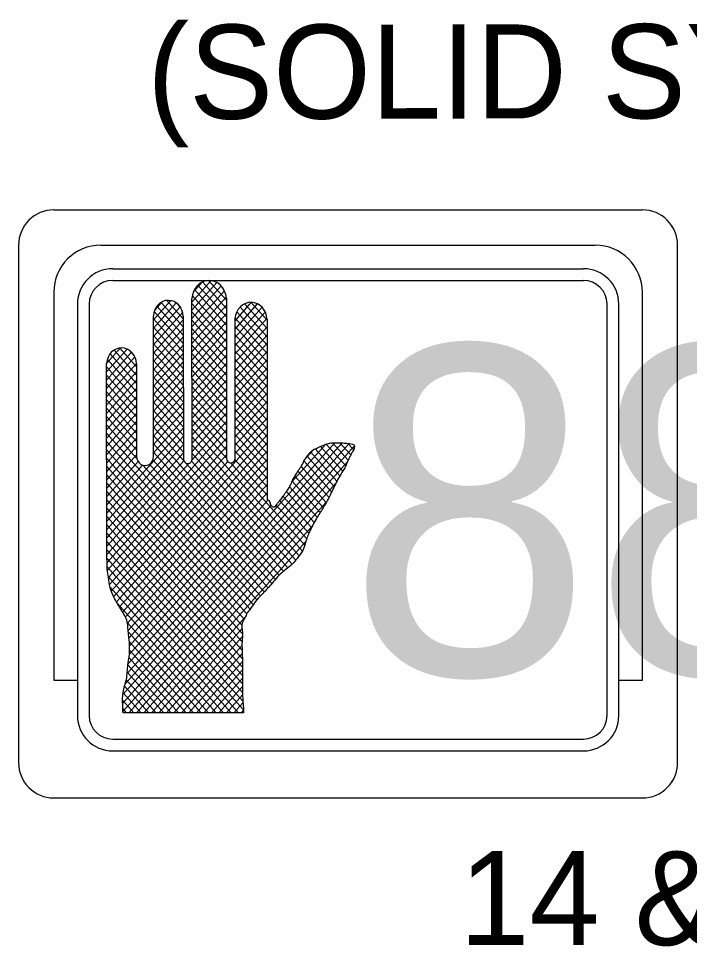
# Model space of a CAD drawing. Extents: x 660636 to 661659, y 641779 to 643841.
# Drawn here: x 660982.79 to 661011.29, y 642847.57 to 642887.02 of the extents above; entities that cross this region are included whole.
import ezdxf

# ---------------------------------------------------------------- set-up
doc = ezdxf.new("R2010")
doc.units = 0
doc.layers.add('Default', color=7, linetype='Continuous')
doc.layers.add('T_Drafting', color=7, linetype='Continuous')

msp = doc.modelspace()

# ---------------------------------------------------------------- linework, layer by layer
at = {"layer": 'T_Drafting'}
for p, q in [((660984.288, 642878.883), (661009.288, 642878.883)), ((660982.788, 642877.383), (660982.788, 642855.383)), ((660986.288, 642877.383), (661007.288, 642877.383)), ((661010.788, 642855.383), (661010.788, 642877.383)), ((660986.788, 642876.383), (661006.788, 642876.383)), ((660986.788, 642875.883), (661006.788, 642875.883)), ((660990.152, 642874.967), (660990.974, 642875.88)), ((660990.153, 642874.614), (660991.218, 642875.797)), ((660990.153, 642874.261), (660991.402, 642875.649)), ((660990.206, 642875.38), (660990.607, 642875.826)), ((660990.403, 642875.687), (660991.616, 642874.339)), ((660990.599, 642875.823), (660991.616, 642874.693)), ((660990.86, 642875.886), (660991.616, 642875.047)), ((660991.327, 642875.721), (660991.469, 642875.564)), ((660984.288, 642875.383), (660984.288, 642858.883)), ((660990.154, 642873.908), (660991.536, 642875.444)), ((660990.167, 642875.242), (660991.617, 642873.631)), ((660990.258, 642875.495), (660991.617, 642873.985)), ((661009.288, 642858.883), (661009.288, 642875.383)), ((660985.288, 642874.883), (660985.288, 642857.383)), ((660985.788, 642874.883), (660985.788, 642857.383)), ((660988.514, 642874.208), (660989.251, 642875.027)), ((660988.515, 642873.855), (660989.484, 642874.931)), ((660988.571, 642874.625), (660988.882, 642874.97)), ((660988.842, 642874.947), (660989.788, 642873.896)), ((660989.084, 642875.032), (660989.787, 642874.25)), ((660989.509, 642874.913), (660989.678, 642874.725)), ((660990.16, 642868.283), (660990.152, 642875.11)), ((660990.152, 642874.905), (660991.618, 642873.277)), ((660990.154, 642873.555), (660991.612, 642875.174)), ((660991.615, 642875.129), (660991.623, 642868.351)), ((660991.983, 642874.172), (660992.688, 642874.956)), ((660991.983, 642873.819), (660992.945, 642874.888)), ((660992.39, 642874.894), (660993.344, 642873.834)), ((660992.651, 642874.957), (660993.344, 642874.188)), ((661007.788, 642857.383), (661007.788, 642874.883)), ((661008.288, 642857.383), (661008.288, 642874.883)), ((660988.515, 642873.501), (660989.652, 642874.765)), ((660988.515, 642873.148), (660989.761, 642874.532)), ((660988.549, 642874.565), (660989.788, 642873.188)), ((660988.666, 642874.789), (660989.788, 642873.542)), ((660990.153, 642874.551), (660991.618, 642872.923)), ((660990.154, 642873.202), (660991.616, 642874.826)), ((660990.155, 642872.849), (660991.616, 642874.473)), ((660991.983, 642873.466), (660993.135, 642874.745)), ((660991.984, 642873.113), (660993.27, 642874.542)), ((660992.059, 642874.554), (660993.345, 642873.126)), ((660992.197, 642874.754), (660993.344, 642873.48)), ((660988.521, 642868.41), (660988.514, 642874.375)), ((660988.514, 642874.251), (660989.789, 642872.834)), ((660988.516, 642872.795), (660989.787, 642874.208)), ((660989.787, 642874.361), (660989.793, 642868.315)), ((660990.153, 642874.197), (660991.618, 642872.569)), ((660990.155, 642872.495), (660991.617, 642874.119)), ((660991.989, 642868.318), (660991.983, 642874.266)), ((660991.984, 642874.284), (660993.345, 642872.772)), ((660991.984, 642872.76), (660993.341, 642874.268)), ((660993.344, 642874.219), (660993.352, 642866.562)), ((660988.514, 642873.897), (660989.789, 642872.48)), ((660988.516, 642872.442), (660989.788, 642873.855)), ((660990.154, 642873.843), (660991.619, 642872.215)), ((660990.156, 642872.142), (660991.617, 642873.766)), ((660991.983, 642873.932), (660993.345, 642872.418)), ((660991.985, 642872.407), (660993.344, 642873.917)), ((660988.515, 642873.543), (660989.79, 642872.126)), ((660988.517, 642872.089), (660989.788, 642873.502)), ((660990.154, 642873.489), (660991.619, 642871.861)), ((660990.156, 642871.789), (660991.618, 642873.413)), ((660991.983, 642873.578), (660993.346, 642872.064)), ((660991.985, 642872.054), (660993.344, 642873.564)), ((660986.526, 642872.352), (660987.121, 642873.014)), ((660986.526, 642871.999), (660987.396, 642872.966)), ((660986.846, 642872.922), (660987.8, 642871.862)), ((660987.085, 642873.01), (660987.799, 642872.216)), ((660987.488, 642872.916), (660987.71, 642872.669)), ((660988.515, 642873.189), (660989.79, 642871.772)), ((660988.517, 642871.736), (660989.789, 642873.149)), ((660990.154, 642873.135), (660991.62, 642871.507)), ((660990.156, 642871.436), (660991.618, 642873.06)), ((660991.984, 642873.224), (660993.346, 642871.71)), ((660991.984, 642872.87), (660993.346, 642871.356)), ((660991.985, 642871.701), (660993.345, 642873.211)), ((660986.527, 642871.646), (660987.592, 642872.83)), ((660986.527, 642871.293), (660987.73, 642872.629)), ((660986.558, 642872.535), (660987.8, 642871.154)), ((660986.673, 642872.761), (660987.8, 642871.508)), ((660988.516, 642872.835), (660989.79, 642871.418)), ((660988.516, 642872.481), (660989.791, 642871.064)), ((660988.517, 642871.383), (660989.789, 642872.796)), ((660990.155, 642872.781), (660991.62, 642871.153)), ((660990.157, 642871.083), (660991.618, 642872.707)), ((660991.984, 642872.516), (660993.347, 642871.002)), ((660991.986, 642871.347), (660993.345, 642872.858)), ((660991.986, 642870.994), (660993.345, 642872.505)), ((660986.535, 642864.112), (660986.526, 642872.355)), ((660986.526, 642872.217), (660987.801, 642870.8)), ((660986.527, 642870.94), (660987.799, 642872.352)), ((660987.799, 642872.34), (660987.803, 642868.409)), ((660988.516, 642872.127), (660989.791, 642870.71)), ((660988.518, 642871.03), (660989.789, 642872.443)), ((660988.518, 642870.677), (660989.79, 642872.089)), ((660990.155, 642872.427), (660991.62, 642870.799)), ((660990.156, 642872.073), (660991.621, 642870.445)), ((660990.157, 642870.73), (660991.619, 642872.354)), ((660991.985, 642872.162), (660993.347, 642870.648)), ((660991.987, 642870.641), (660993.346, 642872.151)), ((660986.526, 642871.863), (660987.801, 642870.446)), ((660986.528, 642870.586), (660987.8, 642871.999)), ((660988.517, 642871.773), (660989.792, 642870.356)), ((660988.519, 642870.323), (660989.79, 642871.736)), ((660990.156, 642871.719), (660991.621, 642870.091)), ((660990.158, 642870.377), (660991.619, 642872.001)), ((660991.985, 642871.808), (660993.348, 642870.294)), ((660991.987, 642870.288), (660993.346, 642871.798)), ((660986.527, 642871.509), (660987.802, 642870.092)), ((660986.528, 642870.233), (660987.8, 642871.646)), ((660986.529, 642869.88), (660987.8, 642871.293)), ((660988.517, 642871.419), (660989.792, 642870.002)), ((660988.519, 642869.97), (660989.791, 642871.383)), ((660990.156, 642871.365), (660991.622, 642869.737)), ((660990.158, 642870.024), (660991.619, 642871.648)), ((660990.158, 642869.671), (660991.62, 642871.295)), ((660991.986, 642871.454), (660993.348, 642869.94)), ((660991.987, 642869.935), (660993.346, 642871.445)), ((660986.527, 642871.155), (660987.802, 642869.738)), ((660986.529, 642869.527), (660987.801, 642870.94)), ((660988.518, 642871.065), (660989.792, 642869.648)), ((660988.519, 642869.617), (660989.791, 642871.03)), ((660990.157, 642871.011), (660991.622, 642869.383)), ((660990.159, 642869.317), (660991.62, 642870.941)), ((660991.986, 642871.1), (660993.348, 642869.586)), ((660991.988, 642869.582), (660993.347, 642871.092)), ((660986.528, 642870.801), (660987.802, 642869.384)), ((660986.529, 642869.174), (660987.801, 642870.587)), ((660988.518, 642870.711), (660989.793, 642869.294)), ((660988.52, 642869.264), (660989.791, 642870.677)), ((660990.157, 642870.657), (660991.622, 642869.029)), ((660990.159, 642868.964), (660991.621, 642870.588)), ((660991.986, 642870.746), (660993.349, 642869.232)), ((660991.988, 642869.229), (660993.347, 642870.739)), ((660986.528, 642870.447), (660987.803, 642869.03)), ((660986.53, 642868.821), (660987.802, 642870.234)), ((660988.518, 642870.357), (660989.793, 642868.94)), ((660988.52, 642868.911), (660989.792, 642870.324)), ((660990.158, 642870.303), (660991.623, 642868.675)), ((660990.16, 642868.611), (660991.621, 642870.235)), ((660991.987, 642870.392), (660993.349, 642868.878)), ((660991.989, 642868.876), (660993.347, 642870.386)), ((660986.528, 642870.093), (660987.803, 642868.676)), ((660986.529, 642869.739), (660987.815, 642868.31)), ((660986.53, 642868.468), (660987.802, 642869.881)), ((660988.519, 642870.003), (660989.794, 642868.586)), ((660988.521, 642868.558), (660989.792, 642869.971)), ((660990.156, 642868.254), (660991.621, 642869.882)), ((660990.158, 642869.949), (660991.618, 642868.327)), ((660991.987, 642870.038), (660993.349, 642868.524)), ((660991.989, 642868.523), (660993.348, 642870.032)), ((660986.529, 642869.385), (660992.907, 642862.299)), ((660986.53, 642868.115), (660987.802, 642869.528)), ((660986.533, 642865.996), (660989.793, 642869.618)), ((660986.547, 642863.89), (660991.622, 642869.529)), ((660986.828, 642862.434), (660993.348, 642869.679)), ((660986.951, 642862.218), (660993.349, 642869.326)), ((660988.519, 642869.649), (660989.81, 642868.215)), ((660990.158, 642869.595), (660994.852, 642864.38)), ((660991.988, 642869.684), (660993.35, 642868.171)), ((660991.988, 642869.33), (660993.35, 642867.817)), ((660986.53, 642869.031), (660992.759, 642862.109)), ((660986.531, 642867.761), (660987.803, 642869.175)), ((660986.533, 642865.643), (660989.793, 642869.265)), ((660986.558, 642863.549), (660991.622, 642869.176)), ((660987.076, 642862.003), (660993.349, 642868.973)), ((660987.221, 642858.275), (660996.826, 642868.948)), ((660987.326, 642858.745), (660996.537, 642868.98)), ((660987.396, 642859.177), (660996.219, 642868.98)), ((660988.52, 642869.295), (660993.866, 642863.354)), ((660988.52, 642868.941), (660993.709, 642863.175)), ((660990.159, 642869.241), (660994.713, 642864.181)), ((660991.988, 642868.976), (660993.35, 642867.463)), ((660994.39, 642867.302), (660995.846, 642868.919)), ((660995.855, 642868.923), (660996.686, 642867.999)), ((660996.121, 642868.98), (660996.788, 642868.24)), ((660996.439, 642868.98), (660996.901, 642868.468)), ((660996.781, 642868.954), (660997.012, 642868.698)), ((660986.53, 642868.677), (660992.625, 642861.905)), ((660986.531, 642867.408), (660987.803, 642868.821)), ((660986.534, 642865.289), (660989.793, 642868.911)), ((660986.534, 642864.936), (660989.794, 642868.558)), ((660986.607, 642863.25), (660991.623, 642868.823)), ((660987.2, 642861.787), (660993.349, 642868.62)), ((660987.211, 642857.91), (660997.057, 642868.85)), ((660988.52, 642868.587), (660993.553, 642862.995)), ((660990.159, 642868.887), (660994.563, 642863.994)), ((660990.16, 642868.533), (660994.406, 642863.815)), ((660991.989, 642868.622), (660993.351, 642867.109)), ((660994.992, 642868.323), (660995.334, 642868.703)), ((660995.197, 642868.592), (660996.314, 642867.352)), ((660995.395, 642868.727), (660996.436, 642867.57)), ((660995.619, 642868.831), (660996.564, 642867.781)), ((660986.53, 642868.323), (660992.481, 642861.711)), ((660986.532, 642867.055), (660987.804, 642868.468)), ((660986.532, 642866.702), (660987.866, 642868.185)), ((660986.534, 642864.583), (660989.808, 642868.22)), ((660986.656, 642862.951), (660991.623, 642868.47)), ((660986.72, 642862.668), (660991.681, 642868.18)), ((660987.211, 642857.557), (660996.75, 642868.156)), ((660987.321, 642861.568), (660993.35, 642868.267)), ((660988.495, 642868.262), (660993.391, 642862.821)), ((660990.139, 642868.203), (660994.226, 642863.662)), ((660991.796, 642868.129), (660994.946, 642864.629)), ((660991.982, 642868.276), (660993.351, 642866.755)), ((660994.915, 642868.199), (660996.089, 642866.894)), ((660995.047, 642868.406), (660996.202, 642867.123)), ((660986.531, 642867.969), (660992.37, 642861.481)), ((660986.532, 642866.349), (660988.048, 642868.033)), ((660986.535, 642864.23), (660990.017, 642868.1)), ((660987.415, 642861.319), (660993.35, 642867.914)), ((660988.072, 642868.025), (660993.066, 642862.475)), ((660988.349, 642868.07), (660993.228, 642862.649)), ((660989.901, 642868.113), (660994.038, 642863.517)), ((660994.655, 642867.781), (660995.853, 642866.45)), ((660994.794, 642867.979), (660995.972, 642866.671)), ((660986.531, 642867.615), (660992.286, 642861.221)), ((660987.451, 642861.005), (660993.35, 642867.56)), ((660994.411, 642867.345), (660995.602, 642866.022)), ((660994.531, 642867.565), (660995.731, 642866.232)), ((660986.531, 642867.261), (660992.297, 642860.855)), ((660987.476, 642857.498), (660996.274, 642867.274)), ((660987.481, 642860.686), (660993.351, 642867.207)), ((660994.305, 642867.109), (660995.47, 642865.814)), ((660986.532, 642866.907), (660992.283, 642860.517)), ((660986.532, 642866.553), (660992.283, 642860.163)), ((660987.497, 642859.997), (660993.397, 642866.551)), ((660987.5, 642860.353), (660993.351, 642866.854)), ((660994.033, 642866.705), (660995.23, 642865.374)), ((660994.166, 642866.91), (660995.349, 642865.596)), ((660986.533, 642866.199), (660992.299, 642859.792)), ((660987.441, 642859.581), (660993.514, 642866.327)), ((660987.795, 642857.498), (660995.856, 642866.455)), ((660993.736, 642866.327), (660995.028, 642864.892)), ((660993.885, 642866.516), (660995.122, 642865.14)), ((660986.533, 642865.845), (660992.301, 642859.436)), ((660986.533, 642865.491), (660992.301, 642859.082)), ((660988.113, 642857.499), (660995.274, 642865.455)), ((660986.534, 642865.137), (660992.302, 642858.728)), ((660986.534, 642864.783), (660992.304, 642858.372)), ((660988.432, 642857.499), (660994.991, 642864.787)), ((660986.534, 642864.429), (660992.318, 642858.003)), ((660986.537, 642864.073), (660992.338, 642857.627)), ((660986.549, 642863.706), (660992.131, 642857.504)), ((660986.599, 642863.297), (660991.813, 642857.504)), ((660986.671, 642862.863), (660991.495, 642857.503)), ((660986.982, 642862.164), (660991.177, 642857.503)), ((660988.75, 642857.5), (660992.423, 642861.581)), ((660987.413, 642861.332), (660990.859, 642857.503)), ((660989.069, 642857.5), (660992.293, 642861.082)), ((660987.459, 642860.927), (660990.542, 642857.502)), ((660989.388, 642857.501), (660992.29, 642860.726)), ((660987.491, 642860.538), (660990.224, 642857.502)), ((660989.706, 642857.501), (660992.281, 642860.362)), ((660987.503, 642860.171), (660989.906, 642857.501)), ((660990.025, 642857.501), (660992.289, 642860.017)), ((660987.436, 642859.539), (660989.27, 642857.5)), ((660987.482, 642859.841), (660989.588, 642857.501)), ((660990.343, 642857.502), (660992.301, 642859.677)), ((660987.401, 642859.224), (660988.953, 642857.5)), ((660990.662, 642857.502), (660992.301, 642859.324)), ((660984.288, 642858.883), (660985.288, 642858.883)), ((660987.366, 642858.91), (660988.635, 642857.499)), ((660990.981, 642857.503), (660992.302, 642858.97)), ((661008.288, 642858.883), (661009.288, 642858.883)), ((660987.226, 642858.357), (660987.999, 642857.499)), ((660987.291, 642858.639), (660988.317, 642857.499)), ((660991.299, 642857.503), (660992.302, 642858.617)), ((660991.618, 642857.504), (660992.307, 642858.27)), ((660987.212, 642858.02), (660987.681, 642857.498)), ((660991.936, 642857.504), (660992.322, 642857.932)), ((660987.211, 642857.667), (660987.364, 642857.498)), ((660987.236, 642857.498), (660987.211, 642857.529)), ((660992.316, 642857.505), (660987.236, 642857.498)), ((660992.255, 642857.505), (660992.338, 642857.597)), ((660992.339, 642857.499), (660992.316, 642857.505)), ((660986.788, 642856.383), (661006.788, 642856.383)), ((660986.788, 642855.883), (661006.788, 642855.883)), ((660984.288, 642853.883), (661009.288, 642853.883))]:
    msp.add_line(p, q, dxfattribs=at)
for centre, radius, start, end in [((660984.288, 642877.383), 1.5, 90, 180), ((661009.288, 642877.383), 1.5, 0, 90), ((660986.288, 642875.383), 2, 90, 180), ((661007.288, 642875.383), 2, 0, 90), ((660986.788, 642874.883), 1.5, 90, 180), ((661006.788, 642874.883), 1.5, 0, 90), ((660986.788, 642874.883), 1, 90, 180), ((661006.788, 642874.883), 1, 0, 90), ((660986.788, 642857.383), 1.5, 180, 270), ((660986.788, 642857.383), 1, 180, 270), ((661006.788, 642857.383), 1.5, 270, 0), ((661006.788, 642857.383), 1, 270, 0), ((660984.288, 642855.383), 1.5, 180, 270), ((661009.288, 642855.383), 1.5, 270, 0)]:
    msp.add_arc(centre, radius, start, end, dxfattribs=at)
for centre, major_axis, start_param, end_param in [((660990.884, 642875.072), (0, -0.814), 1.640121, 4.665593), ((660989.15, 642874.327), (0, -0.709), 1.618611, 4.644084), ((660992.662, 642874.199), (0, -0.758), 1.597842, 4.623315), ((660987.162, 642872.307), (0, -0.709), 1.618611, 4.644084), ((660988.162, 642868.41), (0, -0.398), 4.713646, 7.855239), ((660989.977, 642868.299), (0, -0.204), 4.633755, 7.775348), ((660991.804, 642868.336), (0, -0.207), 4.624552, 7.766145)]:
    msp.add_ellipse(centre, major_axis=major_axis, ratio=0.9, start_param=start_param, end_param=end_param, dxfattribs=at)
for points in [[(660993.351, 642866.563), (660993.403, 642866.549), (660993.472, 642866.394), (660993.56, 642866.275), (660993.613, 642866.256), (660993.7, 642866.276), (660993.754, 642866.356), (660993.912, 642866.55), (660994.035, 642866.708), (660994.105, 642866.824), (660994.175, 642866.922), (660994.298, 642867.098), (660994.368, 642867.255), (660994.474, 642867.47), (660994.545, 642867.588), (660994.668, 642867.802), (660994.807, 642867.999), (660994.913, 642868.194), (660995.035, 642868.389), (660995.142, 642868.527), (660995.298, 642868.684), (660995.492, 642868.763), (660995.598, 642868.822), (660995.756, 642868.879), (660995.897, 642868.94), (660996.109, 642868.98), (660996.284, 642868.98), (660996.513, 642868.98), (660996.725, 642868.961), (660996.97, 642868.922), (660997.041, 642868.881), (660997.057, 642868.824), (660996.954, 642868.57), (660996.883, 642868.432), (660996.814, 642868.294), (660996.743, 642868.139), (660996.707, 642868.041), (660996.567, 642867.786), (660996.357, 642867.434), (660996.075, 642866.867), (660995.724, 642866.219), (660995.444, 642865.769), (660995.285, 642865.476), (660995.146, 642865.201), (660995.063, 642864.983), (660995.02, 642864.872), (660994.863, 642864.4), (660994.619, 642864.067), (660994.425, 642863.833), (660994.144, 642863.596), (660993.968, 642863.459), (660993.511, 642862.949), (660993.108, 642862.52), (660992.844, 642862.225), (660992.615, 642861.891), (660992.501, 642861.746), (660992.405, 642861.541), (660992.299, 642861.344), (660992.299, 642860.914), (660992.283, 642860.528), (660992.283, 642860.174), (660992.301, 642859.706), (660992.301, 642859.256), (660992.302, 642858.532), (660992.321, 642857.949), (660992.338, 642857.733), (660992.338, 642857.575), (660992.338, 642857.5)], [(660987.211, 642857.529), (660987.211, 642857.843), (660987.227, 642858.371), (660987.367, 642858.919), (660987.436, 642859.545), (660987.489, 642859.897), (660987.488, 642860.582), (660987.435, 642861.149), (660987.381, 642861.442), (660987.118, 642861.93), (660986.836, 642862.42), (660986.677, 642862.831), (660986.605, 642863.261), (660986.552, 642863.594), (660986.551, 642863.808), (660986.535, 642864.112)]]:
    msp.add_spline(points, degree=3, dxfattribs=at)

# ---------------------------------------------------------------- texts
at = {"layer": 'Default'}
msp.add_text('14 & 15', height=4, dxfattribs=at).set_placement((661001.52, 642847.627))
at = {"layer": 'T_Drafting'}
for s, height, p in [('(SOLID SYMBOL)', 4, (660988.254, 642882.751)), ('88', 14, (660996.753, 642859.104))]:
    msp.add_text(s, height=height, rotation=0.072, dxfattribs=at).set_placement(p)

doc.saveas('drawing.dxf')
